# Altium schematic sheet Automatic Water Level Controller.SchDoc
size A; SheetNumber: 1; SheetTotal: 1
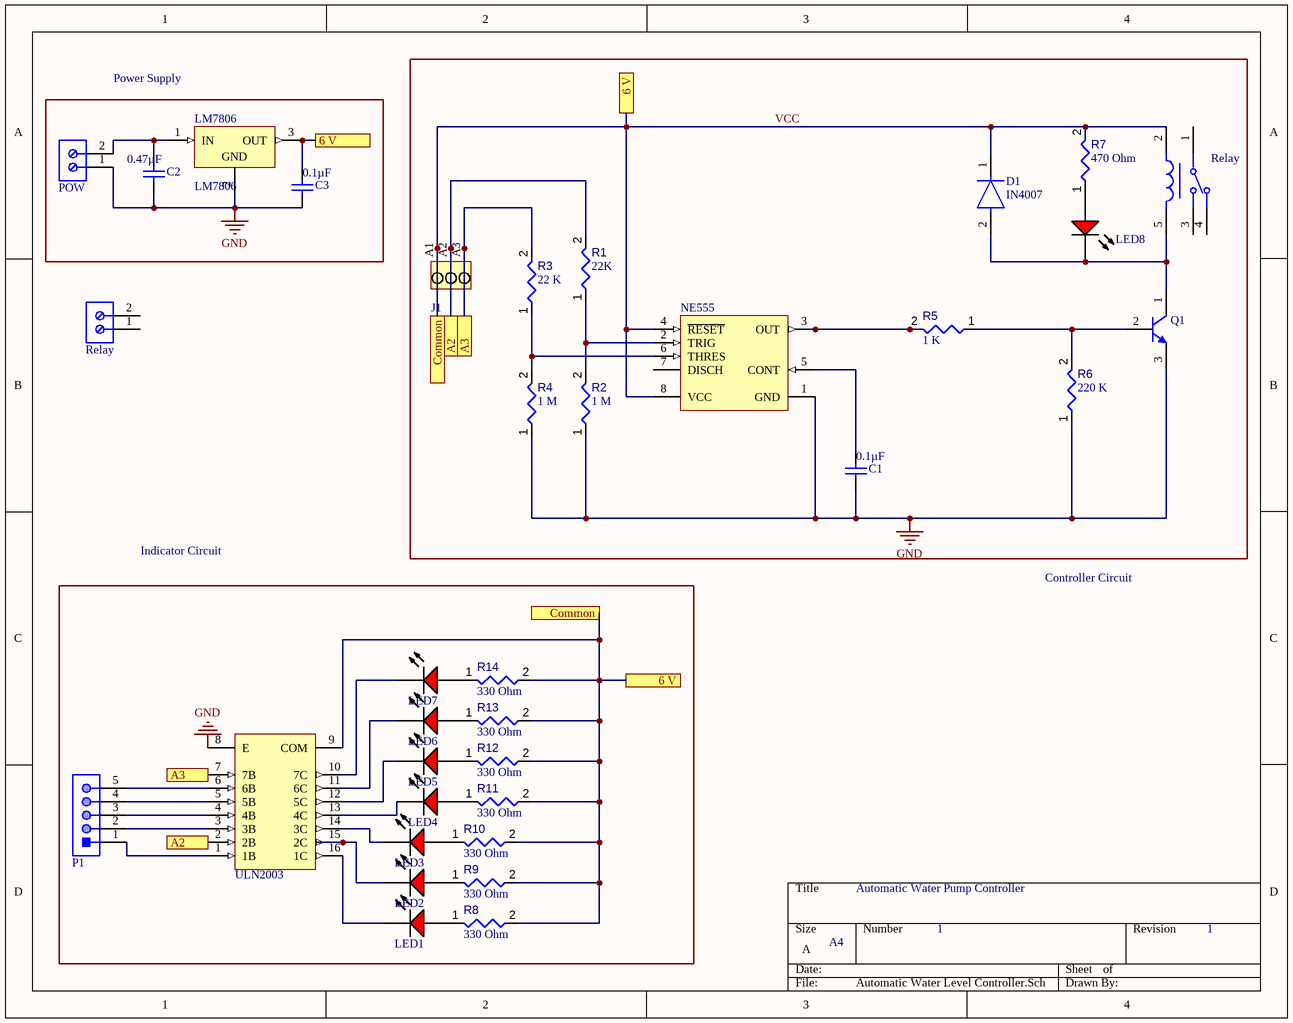
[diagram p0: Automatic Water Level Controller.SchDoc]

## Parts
(Parts that share a designator on the sheet are numbered #1, #2 ... from top to bottom, then left to right.)
C1  Capacitance: 0.1µF  [VISH-K104K15X7RF5TL2]  (hidden comment: K104K15X7RF5TL2)
C2  Capacitance: 0.47µF  [KEMT-C330C105M5U5TA]  (hidden comment: C330C105M5U5TA)
C3  Capacitance: 0.1µF  [KEMT-C330C105M5U5TA]  (hidden comment: C330C105M5U5TA)
D1  IN4007  [FP-1N4007-MFG]
J1  1715320000  [LM_5_00_90_03]  (value not drawn)
LED1  HLMP-3301  [AVAG-HLMP-3301-2]  (value not drawn)
LED2  HLMP-3301  [AVAG-HLMP-3301-2]  (value not drawn)
LED3  HLMP-3301  [AVAG-HLMP-3301-2]  (value not drawn)
LED4  HLMP-3301  [AVAG-HLMP-3301-2]  (value not drawn)
LED5  HLMP-3301  [AVAG-HLMP-3301-2]  (value not drawn)
LED6  HLMP-3301  [AVAG-HLMP-3301-2]  (value not drawn)
LED7  HLMP-3301  [AVAG-HLMP-3301-2]  (value not drawn)
LED8  HLMP-3301  [AVAG-HLMP-3301-2]  (value not drawn)
LM7806  LM7806  [FAIR-TO-220-3]
NE555  NE555  [P0008A]  (value not drawn)
P1  691311700105  [691311700105]  (value not drawn)
POW  691102710002  [691102710002]  (value not drawn)
Q1  BC547BRL1G  [ONSC-TO-92-3-29-11_AM_BL]  (value not drawn)
R1  value 22K  [RESA60-630X240]  (hidden comment: MFR-25FBF52-475K)
R2  value 1 M  [RESA60-630X240]  (hidden comment: MFR-25FBF52-475K)
R3  value 22 K  [RESA60-630X240]  (hidden comment: MFR-25FBF52-475K)
R4  value 1 M  [RESA60-630X240]  (hidden comment: MFR-25FBF52-475K)
R5  value 1 K  [RESA60-630X240]  (hidden comment: MFR-25FBF52-475K)
R6  value 220 K  [RESA60-630X240]  (hidden comment: MFR-25FBF52-475K)
R7  value 470 Ohm  [RESA60-630X240]  (hidden comment: MFR-25FBF52-475K)
R8  value 330 Ohm  [RESA60-630X240]  (hidden comment: MFR-25FBF52-475K)
R9  value 330 Ohm  [RESA60-630X240]  (hidden comment: MFR-25FBF52-475K)
R10  value 330 Ohm  [RESA60-630X240]  (hidden comment: MFR-25FBF52-475K)
R11  value 330 Ohm  [RESA60-630X240]  (hidden comment: MFR-25FBF52-475K)
R12  value 330 Ohm  [RESA60-630X240]  (hidden comment: MFR-25FBF52-475K)
R13  value 330 Ohm  [RESA60-630X240]  (hidden comment: MFR-25FBF52-475K)
R14  value 330 Ohm  [RESA60-630X240]  (hidden comment: MFR-25FBF52-475K)
Relay#1  G5LE-14-DC5  [FP-G5LE-14-DC5-MFG]  (value not drawn)
Relay#2  691102710002  [691102710002]  (value not drawn)
ULN2003  ULN2003AN  [N0016A]  (value not drawn)

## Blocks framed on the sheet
Power Supply: C2 C3 LM7806 POW

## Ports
6 V (see Automatic Water Level Controller[1A], Automatic Water Level Controller[2A]), 6 V (see Automatic Water Level Controller[1A], Automatic Water Level Controller[2C]), 6 V (see Automatic Water Level Controller[2A], Automatic Water Level Controller[2C]), A2 (see Automatic Water Level Controller[1D]), A2 (see Automatic Water Level Controller[2B]), A3 (see Automatic Water Level Controller[1D]), A3 (see Automatic Water Level Controller[2B]), Common (see Automatic Water Level Controller[2B]), Common (see Automatic Water Level Controller[2C])

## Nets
GND: C1.1 C2.1 C3.1 LM7806.2(GND) NE555.1(GND) POW.1 Q1.3(E) R2.1 R4.1 R6.1 ULN2003.8(E)
A2: J1.A2 R1.2 ULN2003.2(2B) ; port A2
A3: J1.A3 R3.2 ULN2003.7(7B) ; port A3
VCC: C3.2 D1.1(C) J1.A1 LM7806.3(OUT) NE555.4(~{RESET}) NE555.8(VCC) R7.2 R8.2 R9.2 R10.2 R11.2 R12.2 R13.2 R14.2 Relay#1.2 ULN2003.9(COM) ; port 6 V, port Common
NetC1_2: C1.2 NE555.5(CONT)
NetC2_2: C2.2 LM7806.1(IN) POW.2
NetD1_2: D1.2(A) LED8.1(K) Q1.1(C) Relay#1.5
NetLED1_1: LED1.1(K) ULN2003.16(1C)
NetLED1_2: LED1.2(A) R8.1
NetLED2_1: LED2.1(K) ULN2003.15(2C)
NetLED2_2: LED2.2(A) R9.1
NetLED3_1: LED3.1(K) ULN2003.14(3C)
NetLED3_2: LED3.2(A) R10.1
NetLED4_1: LED4.1(K) ULN2003.13(4C)
NetLED4_2: LED4.2(A) R11.1
NetLED5_1: LED5.1(K) ULN2003.12(5C)
NetLED5_2: LED5.2(A) R12.1
NetLED6_1: LED6.1(K) ULN2003.11(6C)
NetLED6_2: LED6.2(A) R13.1
NetLED7_1: LED7.1(K) ULN2003.10(7C)
NetLED7_2: LED7.2(A) R14.1
NetLED8_2: LED8.2(A) R7.1
NetNE555_2: NE555.2(TRIG) R1.1 R2.2
NetNE555_3: NE555.3(OUT) R5.2
NetNE555_6: NE555.6(THRES) R3.1 R4.2
NetP1_1: P1.1 ULN2003.1(1B)
NetP1_2: P1.2 ULN2003.3(3B)
NetP1_3: P1.3 ULN2003.4(4B)
NetP1_4: P1.4 ULN2003.5(5B)
NetP1_5: P1.5 ULN2003.6(6B)
NetQ1_2: Q1.2(B) R5.1 R6.2

Not connected (* = marked no-connect by the designer): NE555 7(DISCH); Relay#1 1 3 4; Relay#2 1 2

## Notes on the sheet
- Indicator Circuit
- Controller Circuit
- Automatic Water Pump Controller
- A4
- 1

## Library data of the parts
C1 = CMP-2000-06508-1: Ceramic Capacitor, 100 nF, +/- 10%, 50 V, -55 to 125 degC, 2-Pin THD, RoHS, Tape and Reel; Manufacturer: Vishay; Other Names: BC1084CT; Catalog Drawings: Mono-KapSide2-15_5.58Mono-KapSide1_15; Temperature Coefficient: X7R; Voltage - Rated: 50V; Online Catalog: Mono-Kap™Series
C2 C3 = CMP-2000-06056-1: Ceramic Capacitor, 1 uF, +/- 20%, 50 V, -10 to 85 degC, 2-Pin THD, RoHS, Bulk; Manufacturer: Kemet; Voltage - Rated: 50V; Temperature Coefficient: Z5U; Catalog Drawings: C330(std); Product Training Modules: CapacitorBasics-TypicalUsesforCapacitors; Online Catalog: GoldenMax™Series; Other Names: 399-4390; PCN Design/Specification: C3yySeriesGoldenMaxLeadConfiguration02/Feb/2015
D1 = CMP-02540-000046-1: DIODE GEN PURP 1KV 1A DO204AL; Manufacturer: Vishay; Manufacturer Part Number: 1N4007-E3/54; Value: 15pF; Max Junction Temp: +150°C; Max Surge Forward Current: 30A; Max Repetitive Reverse Voltage: 1000V; Peak Reverse Current: 30uA
J1 = CMP-1559-01747-1: OMNIMATE Signal - series LM; Manufacturer: Weidmueller; UL_94_flammability_rating: V-0; Solid_min_H05_07_V_U: 0,2 mm²; Mounting_onto_the_PCB: Solder connection; Wire_cross_section_AWG_min_UL_1059: AWG 24; Contact_material: Cu-Leg; Wire_cross_section_AWG_max_UL_1059: AWG 14; Rated_voltage_for_surge_voltage_class_pollution_degree_II_2: 630 V; No_of_poles: 3; Short_text_for_material: LM 5.00/03/90 3.5SN OR BX; Solid_max_H05_07_V_U: 2,5 mm²; Insulating_material: Wemid (PA); Rated_current_use_group_B_UL_1059: 15 A; Rated_voltage_use_group_B_UL_1059: 300 V; Contact_surface: tinned; Pitch_inch: 0,197 inch; Pitch_mm: 5 mm; Side_termination_characteristic: closed side; Solder_pin_length_mm: 3,5 mm
LED1-LED8 = CMP-2000-06411-1: T-1 3/4 (5 mm) Diffused LED Lamp, 1.9 V, -40 to 100 degC, 2-Pin THD, RoHS, Bulk; Manufacturer: Avago; Forward Current: 25mA; Forward Voltage: 2.4V; Peak Wavelength: 635nm; Shape Type: Circular; High Brightness: No; Main Category: StandardLED; Test Current (It): 10mA; Dominant Wave Length: 626nm; Number of  Elements: 1; Reverse Voltage: 5V; Chip Material: GaP; Product Height (mm): 9.19mm; Lens Type: ColoredDiffused; Viewing Angle: 60deg; Type: Uni-Color; Emitting Color: Red; Luminous Intensity: 5.4mcd; Power Dissipation: 85W; DELETED: Compliant; Product Depth (mm): 6.1mm
LM7806 = CMP-2000-04938-1: Positive Voltage Regulator, 5 V, 1 A, -40 to 125 degC, 3-Pin TO-220, RoHS, Tube; Manufacturer: FairchildSemiconductor; Maximum Input Voltage: 35V; Maximum Quiescent Current: 8mA; Load Regulation: 100mV; Maximum Output Current: 2.2(Typ)A; Output Type: Fixed; Typical Dropout Voltage @ Current: 2@1AV; Rad Hard: No; Output Voltage: 5V; Accuracy: ±4%; Number of Outputs: 1
NE555 = CMP-2000-04954-1: Precision Timer, 4.5 to 16 V, 0 to 70 degC, 8-Pin DIP, Pb-Free, Tube; Manufacturer: TexasInstruments; Maximum High Level Output Current: -200mA; Number of Internal Timers: 1; Operating Supply Voltage: 5; Maximum Low Level Output Current: 200mA; Rad Hard: No
P1 = CMP-1502-02036-1: Serie 3117 - 5.00mm Close Vertical PCB Header WR-TBL, 5 pin; Manufacturer: Wurth Elektronik; Pin Number: 5; Gender: Male
POW Relay#2 = CMP-1502-03258-1: Series 102 - 5.00 mm Horizontal Entry Modular with Pressure Clamp WR-TBL, 2 pin; Manufacturer: Wurth Elektronik; Pin Number: 2; Pitch: 5.00mm
Q1 = CMP-1048-01605-1: Amplifier Transistor, NPN Silicon, 3-Pin TO-92, Pb-Free, Tape and Reel; Manufacturer: On Semiconductor; IC Continuous (A): 0.1; fT Min (MHz): 150
R1-R14 = CMP-009-00055-4: Axial Resistor, 475 KOhm, +/- 1%, 0.25 W, -55 to 155 degC, 2-Pin THD, RoHS, Bulk; Manufacturer: Yageo; Power: 250mW; Voltage Rating: 250V
Relay#1 = CMP-08822-000008-1: RELAY GEN PURPOSE SPDT 10A 5V; Manufacturer: Omron; Number Of Contacts: 1; Coil Type: Non-Latching; Coil Current: 79.4mA; Coil Power: 400mW; Coil Resistance: 63Ω; Standoff Height: 0.5mm
ULN2003 = CMP-2000-07352-1: High-Voltage, High-Current Darlington Transistor Array, 50 V, 500 mA, -20 to 70 degC, 16-Pin PDIP (N), Pb-Free (RoHS), Tube; Manufacturer: TexasInstruments; Maximum Collector Emitter Saturation Voltage: 1.1@100mA; Peak DC Collector Current: 0.5A; Package Version: 4040049/E, 12/2002; Configuration: Array7; Maximum Collector Emitter Voltage: 50V; Rad Hard: No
